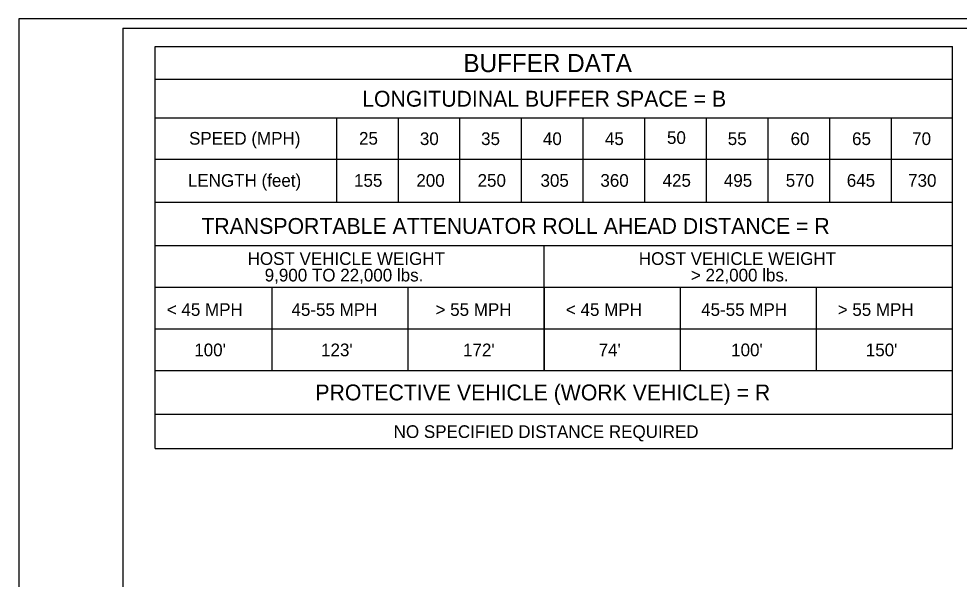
# Model space of a CAD drawing. Extents: x 99988 to 100172, y 99995 to 100047.
# Drawn here: x 99999.31 to 100005.53, y 100006.73 to 100010.44 of the extents above; entities that cross this region are included whole.
import ezdxf

# ---------------------------------------------------------------- set-up
doc = ezdxf.new("R2010")
doc.units = 0
for name, color, linetype in [('SH_GI_PlotLimits', 7, 'Continuous'), ('SH_GI_SheetBorder', 7, 'Continuous'), ('SH_TI_BufferDataNote', 7, 'Continuous')]:
    doc.layers.add(name, color=color, linetype=linetype)

msp = doc.modelspace()

# ---------------------------------------------------------------- linework, layer by layer
at = {"layer": 'SH_GI_PlotLimits'}
msp.add_lwpolyline([(99999.3125, 99999.9375), (100015.8125, 99999.9375), (100015.8125, 100010.4375), (99999.3125, 100010.4375)], close=True, dxfattribs=at)
at = {"layer": 'SH_GI_SheetBorder'}
for q in [(100000, 100000), (100015.75, 100010.375), (100015.75, 100010.375)]:
    msp.add_line((100000, 100010.375), q, dxfattribs=at)
at = {"layer": 'SH_TI_BufferDataNote'}
for p, q in [((100000.2142, 100010.2532), (100005.4875, 100010.2532)), ((100000.2142, 100008.109), (100000.2142, 100010.2532)), ((100005.4875, 100007.593), (100005.4875, 100010.2532)), ((100000.2142, 100010.0386), (100005.4875, 100010.0386)), ((100000.2142, 100009.7814), (100005.4875, 100009.7814)), ((100001.4125, 100009.7814), (100001.4125, 100009.2242)), ((100001.82, 100009.7814), (100001.82, 100009.2242)), ((100002.2275, 100009.7814), (100002.2275, 100009.2242)), ((100002.635, 100009.7814), (100002.635, 100009.2242)), ((100003.0425, 100009.7814), (100003.0425, 100009.2242)), ((100003.45, 100009.7814), (100003.45, 100009.2242)), ((100003.8575, 100009.7814), (100003.8575, 100009.2242)), ((100004.265, 100009.7814), (100004.265, 100009.2242)), ((100004.6725, 100009.7814), (100004.6725, 100009.2242)), ((100005.08, 100009.7814), (100005.08, 100009.2242)), ((100000.2142, 100009.5093), (100005.4875, 100009.5093)), ((100000.2142, 100009.2242), (100005.4875, 100009.2242)), ((100000.2142, 100008.937), (100005.4875, 100008.937)), ((100002.7875, 100008.109), (100002.7875, 100008.9347)), ((100000.2142, 100008.661), (100005.4875, 100008.661)), ((100000.2142, 100007.593), (100000.2142, 100008.661)), ((100000.9877, 100008.109), (100000.9877, 100008.661)), ((100001.8877, 100008.109), (100001.8877, 100008.661)), ((100002.7877, 100008.109), (100002.7877, 100008.661)), ((100003.6877, 100008.109), (100003.6877, 100008.661)), ((100004.5877, 100008.109), (100004.5877, 100008.661)), ((100000.2142, 100008.385), (100005.4875, 100008.385)), ((100000.2142, 100008.109), (100005.4875, 100008.109)), ((100000.2142, 100007.821), (100005.4875, 100007.821)), ((100000.2142, 100007.593), (100005.4875, 100007.593))]:
    msp.add_line(p, q, dxfattribs=at)

# ---------------------------------------------------------------- texts
for s, height, p in [('BUFFER DATA', 0.12, (100002.2521, 100010.0847)), ('LONGITUDINAL BUFFER SPACE = B', 0.105, (100001.583, 100009.8558)), ('SPEED (MPH)', 0.084, (100000.4383, 100009.6043)), ('25', 0.084, (100001.5621, 100009.6043)), ('30', 0.084, (100001.9646, 100009.6019)), ('35', 0.084, (100002.3693, 100009.6019)), ('40', 0.084, (100002.7781, 100009.6019)), ('45', 0.084, (100003.1883, 100009.6019)), ('50', 0.084, (100003.5985, 100009.609)), ('55', 0.084, (100004.0003, 100009.6019)), ('60', 0.084, (100004.4158, 100009.6019)), ('65', 0.084, (100004.8223, 100009.6019)), ('70', 0.084, (100005.2197, 100009.6019)), ('LENGTH (feet)', 0.084, (100000.4307, 100009.3257)), ('155', 0.084, (100001.529, 100009.3257)), ('200', 0.084, (100001.9412, 100009.3257)), ('250', 0.084, (100002.3462, 100009.3257)), ('305', 0.084, (100002.7622, 100009.3257)), ('360', 0.084, (100003.1582, 100009.3257)), ('425', 0.084, (100003.5694, 100009.3257)), ('495', 0.084, (100003.9746, 100009.3257)), ('570', 0.084, (100004.384, 100009.3257)), ('645', 0.084, (100004.7874, 100009.3257)), ('730', 0.084, (100005.193, 100009.3257)), ('TRANSPORTABLE ATTENUATOR ROLL AHEAD DISTANCE = R', 0.105, (100000.52, 100009.0138)), ('HOST VEHICLE WEIGHT', 0.084, (100000.8256, 100008.8084)), ('HOST VEHICLE WEIGHT', 0.084, (100003.4123, 100008.8084)), ('9,900 TO 22,000 lbs.', 0.084, (100000.9385, 100008.6991)), ('> 22,000 lbs.', 0.084, (100003.7567, 100008.6991)), ('< 45 MPH', 0.084, (100000.2909, 100008.4712)), ('45-55 MPH', 0.084, (100001.1155, 100008.4712)), ('> 55 MPH', 0.084, (100002.0681, 100008.4712)), ('< 45 MPH', 0.084, (100002.9302, 100008.4712)), ('45-55 MPH', 0.084, (100003.8244, 100008.4712)), ('> 55 MPH', 0.084, (100004.7274, 100008.4712)), ("100'", 0.084, (100000.4727, 100008.204)), ("123'", 0.084, (100001.3111, 100008.204)), ("172'", 0.084, (100002.25, 100008.204)), ("74'", 0.084, (100003.1466, 100008.204)), ("100'", 0.084, (100004.0229, 100008.204)), ("150'", 0.084, (100004.9132, 100008.204)), ('PROTECTIVE VEHICLE (WORK VEHICLE) = R', 0.105, (100001.2734, 100007.912)), ('NO SPECIFIED DISTANCE REQUIRED', 0.084, (100001.7913, 100007.6631))]:
    msp.add_text(s, height=height, dxfattribs=at).set_placement(p)

doc.saveas('drawing.dxf')
